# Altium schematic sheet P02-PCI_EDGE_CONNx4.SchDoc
size 304 x 220 mm
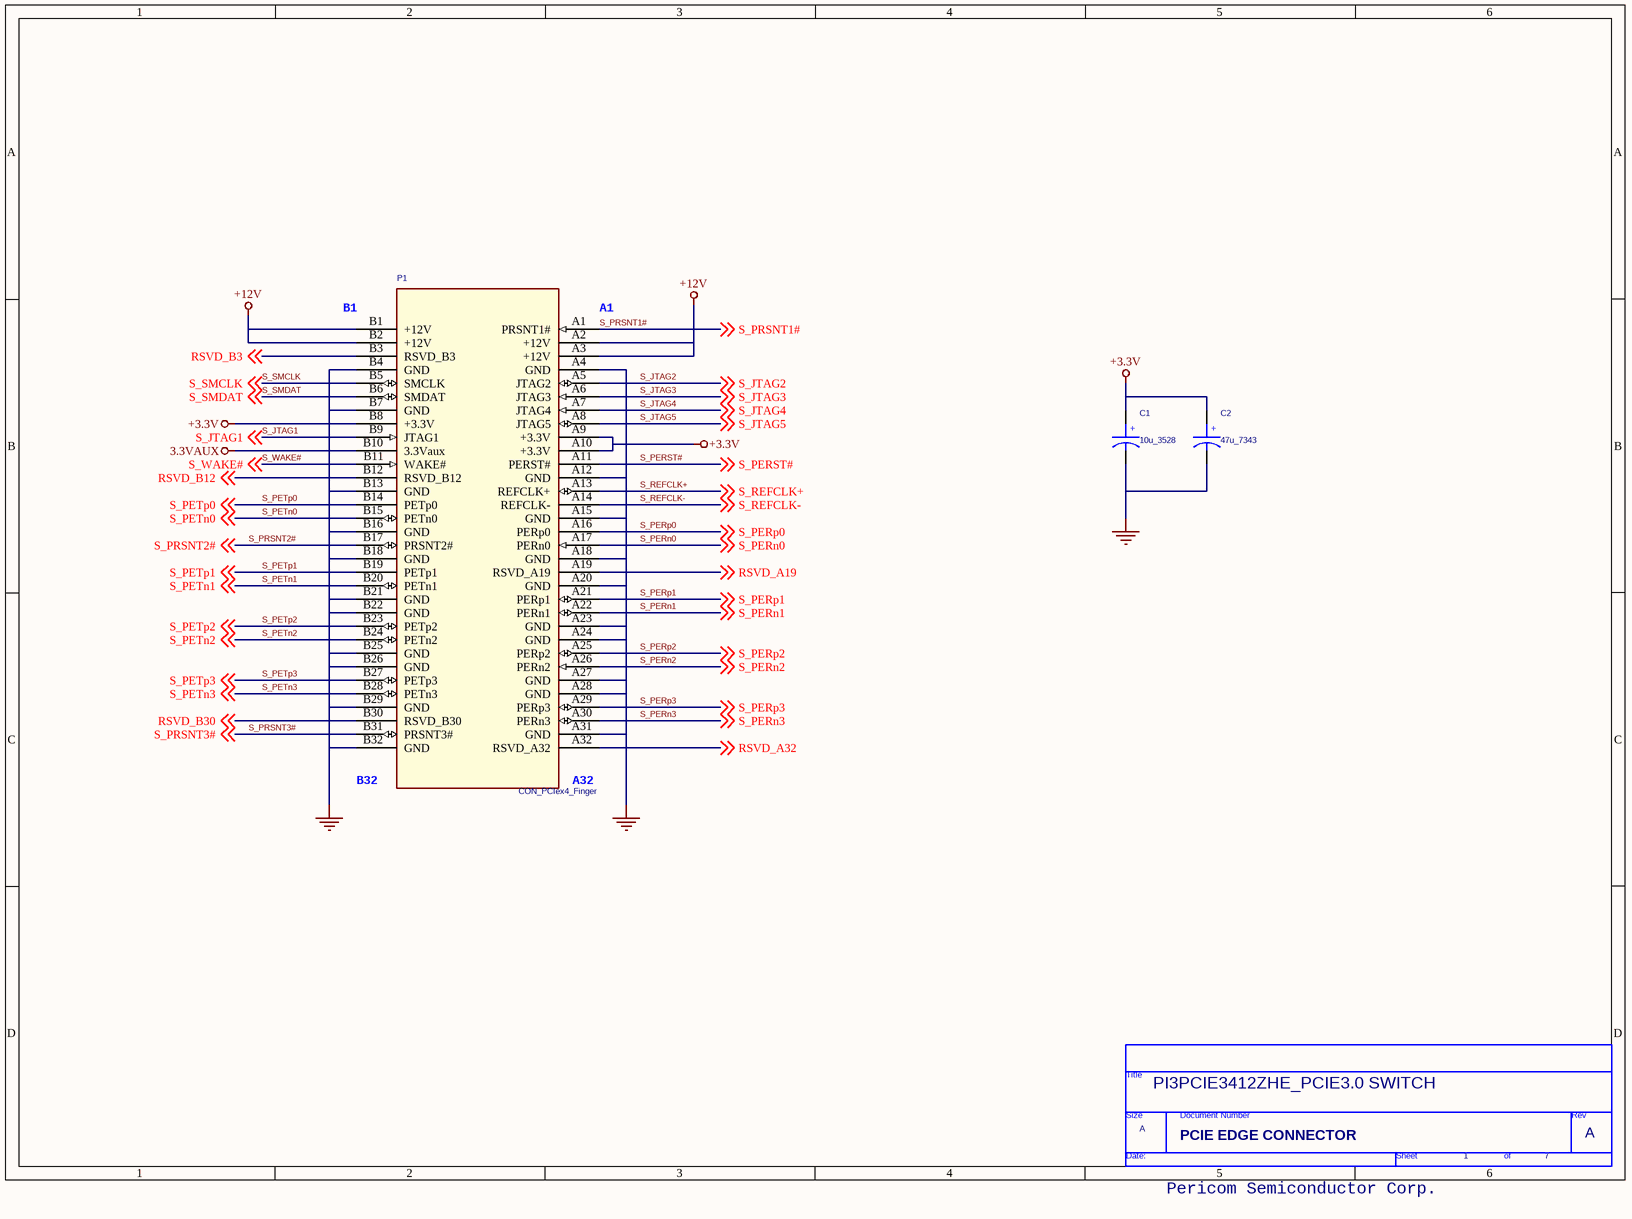
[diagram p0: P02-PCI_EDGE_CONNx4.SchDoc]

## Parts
*  Doc: PCIE EDGE CONNECTOR  RevCode: A  Title: PI3PCIE3412ZHE_PCIE3.0 SWITCH  Page Number: 1  Page Count: 7  (hidden comment: TitleBlock0)  (graphical)
C1  10u_3528  [CT_3528]
C2  47u_7343  [CT_7343]
P1  CON_PCIex4_Finger  [CON_PCIex4_Finger]

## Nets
3.3VAUX: P1.B10(3.3Vaux)
+3.3V: C1.1 C2.1 P1.A9(+3.3V) P1.A10(+3.3V) P1.B8(+3.3V)
+12V: P1.A2(+12V) P1.A3(+12V) P1.B1(+12V) P1.B2(+12V)
GND: C1.2 C2.2 P1.A4(GND) P1.A12(GND) P1.A15(GND) P1.A18(GND) P1.A20(GND) P1.A23(GND) P1.A24(GND) P1.A27(GND) P1.A28(GND) P1.A31(GND) P1.B4(GND) P1.B7(GND) P1.B13(GND) P1.B16(GND) P1.B18(GND) P1.B21(GND) P1.B22(GND) P1.B25(GND) P1.B26(GND) P1.B29(GND) P1.B32(GND)
RSVD_A19: P1.A19(RSVD_A19) ; off-sheet RSVD_A19
RSVD_A32: P1.A32(RSVD_A32) ; off-sheet RSVD_A32
RSVD_B3: P1.B3(RSVD_B3) ; off-sheet RSVD_B3
RSVD_B12: P1.B12(RSVD_B12) ; off-sheet RSVD_B12
RSVD_B30: P1.B30(RSVD_B30) ; off-sheet RSVD_B30
S_JTAG1: P1.B9(JTAG1) ; off-sheet S_JTAG1
S_JTAG2: P1.A5(JTAG2) ; off-sheet S_JTAG2
S_JTAG3: P1.A6(JTAG3) ; off-sheet S_JTAG3
S_JTAG4: P1.A7(JTAG4) ; off-sheet S_JTAG4
S_JTAG5: P1.A8(JTAG5) ; off-sheet S_JTAG5
S_PERn0: P1.A17(PERn0) ; off-sheet S_PERn0
S_PERn1: P1.A22(PERn1) ; off-sheet S_PERn1
S_PERn2: P1.A26(PERn2) ; off-sheet S_PERn2
S_PERn3: P1.A30(PERn3) ; off-sheet S_PERn3
S_PERp0: P1.A16(PERp0) ; off-sheet S_PERp0
S_PERp1: P1.A21(PERp1) ; off-sheet S_PERp1
S_PERp2: P1.A25(PERp2) ; off-sheet S_PERp2
S_PERp3: P1.A29(PERp3) ; off-sheet S_PERp3
S_PERST#: P1.A11(PERST#) ; off-sheet S_PERST#
S_PETn0: P1.B15(PETn0) ; off-sheet S_PETn0
S_PETn1: P1.B20(PETn1) ; off-sheet S_PETn1
S_PETn2: P1.B24(PETn2) ; off-sheet S_PETn2
S_PETn3: P1.B28(PETn3) ; off-sheet S_PETn3
S_PETp0: P1.B14(PETp0) ; off-sheet S_PETp0
S_PETp1: P1.B19(PETp1) ; off-sheet S_PETp1
S_PETp2: P1.B23(PETp2) ; off-sheet S_PETp2
S_PETp3: P1.B27(PETp3) ; off-sheet S_PETp3
S_PRSNT1#: P1.A1(PRSNT1#) ; off-sheet S_PRSNT1#
S_PRSNT2#: P1.B17(PRSNT2#) ; off-sheet S_PRSNT2#
S_PRSNT3#: P1.B31(PRSNT3#) ; off-sheet S_PRSNT3#
S_REFCLK+: P1.A13(REFCLK+) ; off-sheet S_REFCLK+
S_REFCLK-: P1.A14(REFCLK-) ; off-sheet S_REFCLK-
S_SMCLK: P1.B5(SMCLK) ; off-sheet S_SMCLK
S_SMDAT: P1.B6(SMDAT) ; off-sheet S_SMDAT
S_WAKE#: P1.B11(WAKE#) ; off-sheet S_WAKE#

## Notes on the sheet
- Pericom Semiconductor Corp.

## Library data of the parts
C1 = C_tan_22u_3528
C2 = C_tan_100u_7343
P1 = CON_PCIex4_Finger: SDTSourceLibName: C:\WINDOWS\TEMP\CS8.LIB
